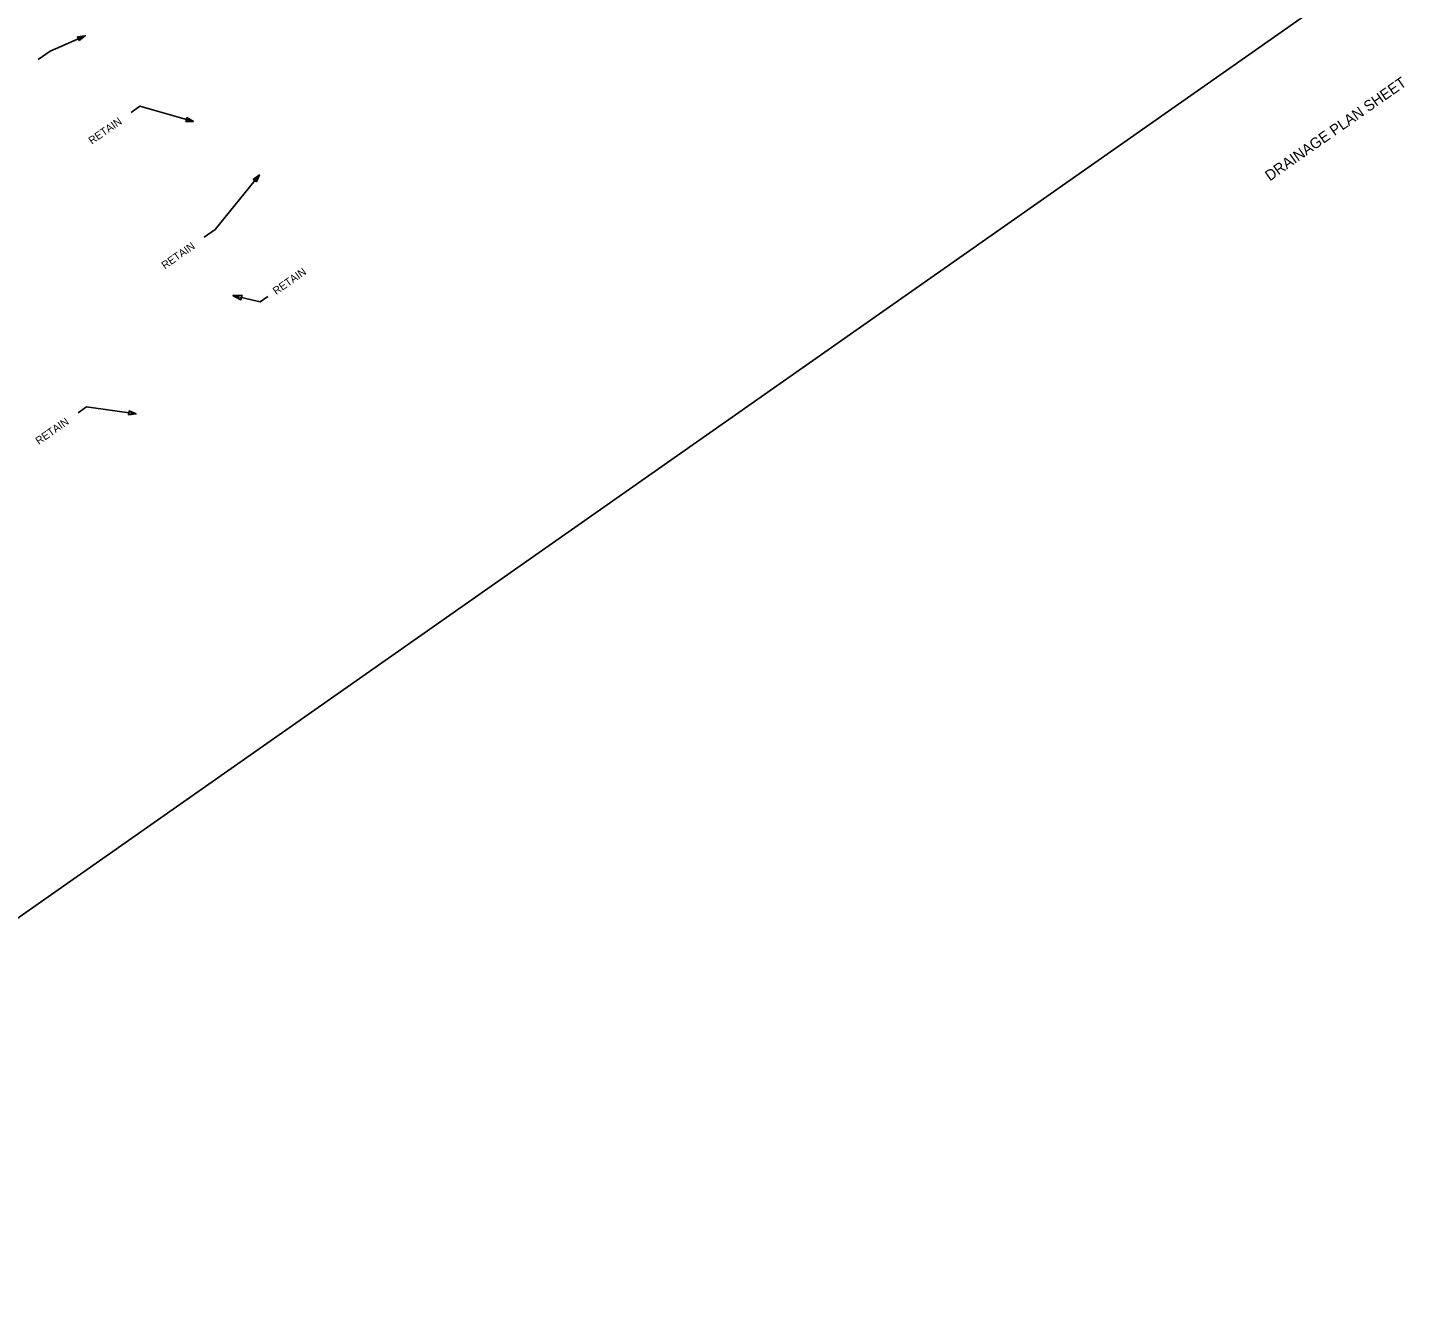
# Model space of a CAD drawing. Extents: x 1605049 to 1606865, y 1089598 to 1091250.
# Drawn here: x 1605969 to 1606865, y 1089598 to 1090437 of the extents above; entities that cross this region are included whole.
import ezdxf

# ---------------------------------------------------------------- set-up
doc = ezdxf.new("R2010")
doc.units = 0
for name, color, linetype in [('Plan_Clip', 7, 'Continuous'), ('RD_TX_Drainage', 7, 'Continuous'), ('RD_TX_RoadID', 7, 'Continuous')]:
    doc.layers.add(name, color=color, linetype=linetype)

msp = doc.modelspace()

# ---------------------------------------------------------------- linework, layer by layer
at = {"layer": 'Plan_Clip'}
msp.add_lwpolyline([(1605233.56, 1090111.04), (1605405.83, 1089865.44), (1605593.12, 1089598.42), (1606815.94, 1090456.14), (1606682.28, 1090657.78), (1606533.03, 1090870.55), (1606535.89, 1090871.82), (1606406.67, 1091049.1), (1606294.17, 1091212.27), (1606168.16, 1091123.23), (1606148, 1091151.76), (1605049.41, 1090375.46)], close=True, dxfattribs=at)
msp.add_lwpolyline([(1605233.56, 1090111.04), (1605405.83, 1089865.44), (1605593.12, 1089598.42), (1606815.94, 1090456.14), (1606682.28, 1090657.78), (1606533.03, 1090870.55), (1606535.89, 1090871.82), (1606406.67, 1091049.1), (1606294.17, 1091212.27), (1606168.16, 1091123.23), (1606148, 1091151.76), (1605049.41, 1090375.46)], close=True, dxfattribs=at)
msp.add_lwpolyline([(1605233.56, 1090111.04), (1605405.83, 1089865.44), (1605593.12, 1089598.42), (1606815.94, 1090456.14), (1606682.28, 1090657.78), (1606533.03, 1090870.55), (1606535.89, 1090871.82), (1606406.67, 1091049.1), (1606294.17, 1091212.27), (1606168.16, 1091123.23), (1606148, 1091151.76), (1605049.41, 1090375.46)], close=True, dxfattribs=at)
msp.add_lwpolyline([(1605233.56, 1090111.04), (1605405.83, 1089865.44), (1605593.12, 1089598.42), (1606815.94, 1090456.14), (1606682.28, 1090657.78), (1606533.03, 1090870.55), (1606535.89, 1090871.82), (1606406.67, 1091049.1), (1606294.17, 1091212.27), (1606168.16, 1091123.23), (1606148, 1091151.76), (1605049.41, 1090375.46)], close=True, dxfattribs=at)
msp.add_lwpolyline([(1605233.56, 1090111.04), (1605405.83, 1089865.44), (1605593.12, 1089598.42), (1606815.94, 1090456.14), (1606682.28, 1090657.78), (1606533.03, 1090870.55), (1606535.89, 1090871.82), (1606406.67, 1091049.1), (1606294.17, 1091212.27), (1606168.16, 1091123.23), (1606148, 1091151.76), (1605049.41, 1090375.46)], close=True, dxfattribs=at)
at = {"layer": 'RD_TX_Drainage'}
for points in [[(1605975.51, 1090416.15), (1605983.26, 1090421.58), (1606006.13, 1090431.59)], [(1606036.02, 1090381.59), (1606041.78, 1090385.63), (1606076.62, 1090375.7)], [(1606083.55, 1090300.37), (1606090.79, 1090305.45), (1606119.6, 1090340.96)], [(1606124.93, 1090261.91), (1606119.99, 1090258.44), (1606102.25, 1090262.56)], [(1606001.5, 1090186.12), (1606006.92, 1090189.93), (1606039.3, 1090185.33)]]:
    msp.add_lwpolyline(points, dxfattribs=at)
for points in [[(1606002.22, 1090428.47), (1606006.13, 1090431.59), (1606001.19, 1090430.84)], [(1606071.62, 1090375.78), (1606076.62, 1090375.7), (1606072.33, 1090378.27)], [(1606117.57, 1090336.4), (1606119.6, 1090340.96), (1606115.56, 1090338.03)], [(1606108.25, 1090262.76), (1606102.25, 1090262.56), (1606107.55, 1090259.74)], [(1606034.34, 1090184.73), (1606039.3, 1090185.33), (1606034.7, 1090187.29)]]:
    msp.add_lwpolyline(points, close=True, dxfattribs=at)

# ---------------------------------------------------------------- texts
for p in [(1606010.48, 1090360.62), (1606058.01, 1090279.4), (1606130.46, 1090262.73), (1605975.95, 1090165.15)]:
    msp.add_text('RETAIN', height=5, rotation=35.04683, dxfattribs=at).set_placement(p)
at = {"layer": 'RD_TX_RoadID'}
msp.add_text('DRAINAGE PLAN SHEET', height=6.9833, rotation=35.04683, dxfattribs=at).set_placement((1606777.34, 1090336.68))

doc.saveas('drawing.dxf')
